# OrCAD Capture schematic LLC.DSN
size A; title: Double Switch Forward Converter; rev: 1
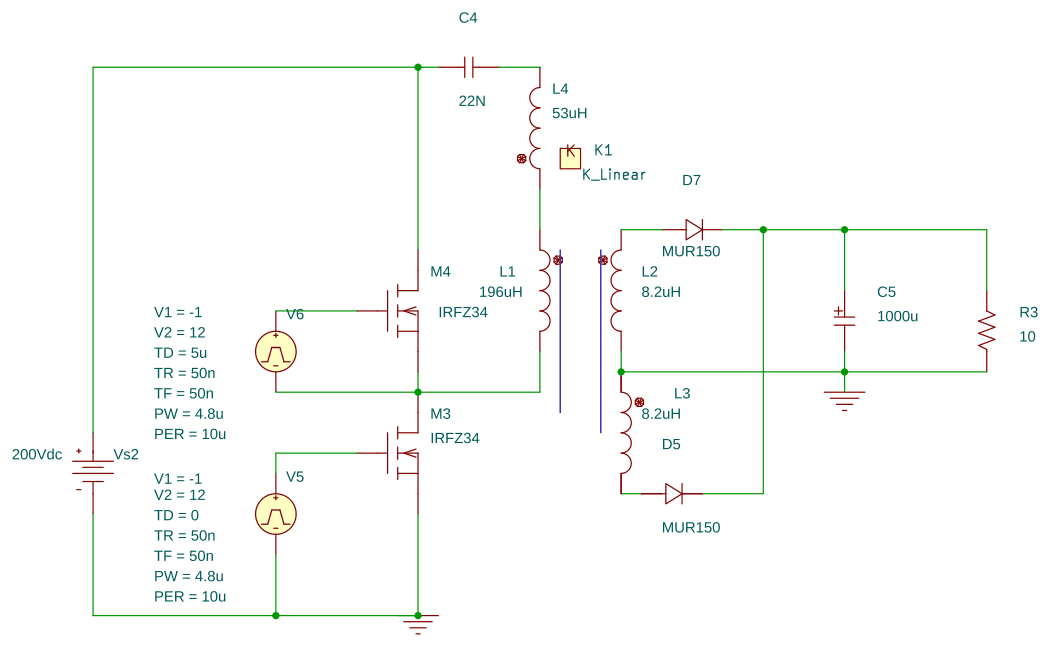
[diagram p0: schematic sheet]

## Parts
C4  22N  [RAD/CK05]
C5  1000u  [CPAX/.575x.150/.031]
D5  MUR150  [DO-41]
D7  MUR150  [DO-41]
K1  K_Linear
L1  196uH  [DISC/.350x.175/LS.200x.100/.034]
L2  8.2uH  [DISC/.350x.175/LS.200x.100/.034]
L3  8.2uH  [DISC/.350x.175/LS.200x.100/.034]
L4  53uH  [DISC/.350x.175/LS.200x.100/.034]
M3  IRFZ34  [TO220AB]
M4  IRFZ34  [TO220AB]
R3  10  [AX/RC05]
V5  VPULSE
V6  VPULSE
Vs2  VDC

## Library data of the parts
C4 = C: IC: 75
C5 = C_elect
D5 D7 = MUR150
K1 = K_Linear: COUPLING: 1; L1: L1; L2: L2; L3: L3
L1-L4 = L
M3 M4 = IRFZ34
R3 = R
V5 = VPULSE: PER: 10u; PW: 4.8u; TD: 0; TF: 50n; TR: 50n; V1: -1; V2: 12
V6 = VPULSE: PER: 10u; PW: 4.8u; TD: 5u; TF: 50n; TR: 50n; V1: -1; V2: 12
Vs2 = VDC: DC: 200Vdc

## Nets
0: C5.N(-) L2.2 L3.1 M3.3(s) R3.1 V5.2(-) Vs2.1(-)
N9060211: L1.2 M3.2(d) M4.3(s) V6.2(-)
N9060290: L1.1 L4.1
N9060298: C4.1 M4.2(d) Vs2.0(+)
N9060358: D7.1 L2.1
N9060362: C5.P(+) D5.2 D7.2 R3.2
N9060403: D5.1 L3.2
N9060652: C4.2 L4.2
N9060690: M4.1(g) V6.1(+)
N9060703: M3.1(g) V5.1(+)
